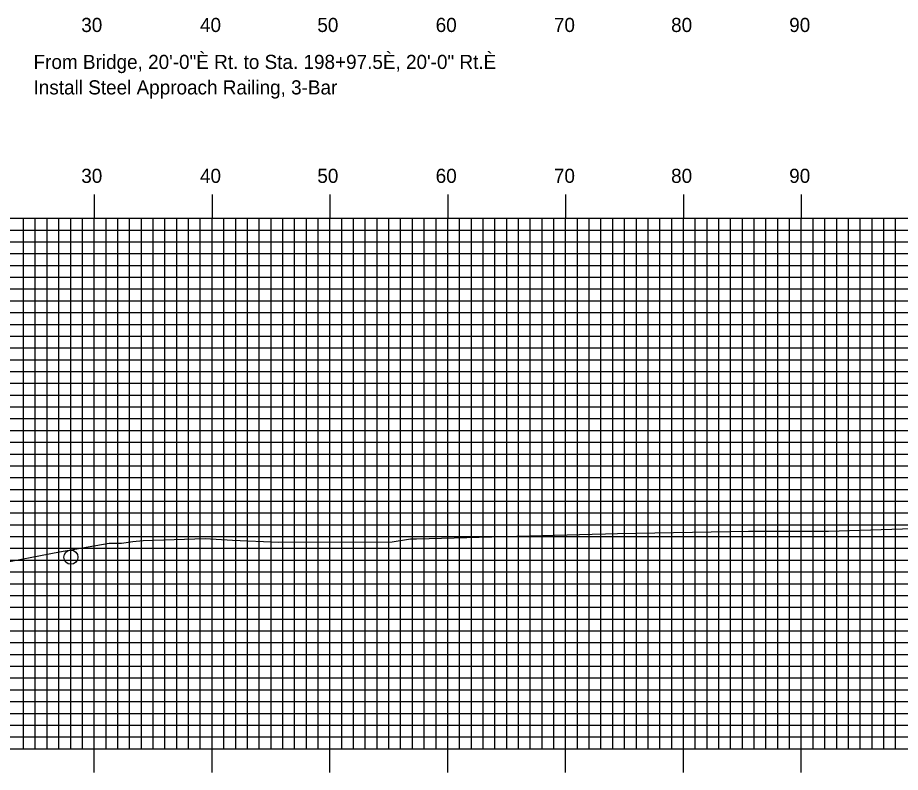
# Model space of a CAD drawing. Extents: x 1790124 to 1790467, y 442591 to 442811.
# Drawn here: x 1790313.2 to 1790388.1, y 442671.7 to 442735.7 of the extents above; entities that cross this region are included whole.
import ezdxf

# ---------------------------------------------------------------- set-up
doc = ezdxf.new("R2010")
doc.units = 0
for name, color, linetype in [('ANNOTATION', 7, 'Continuous'), ('H_V ANNOTATION', 7, 'Continuous'), ('MAJOR', 7, 'Continuous'), ('MINOR', 7, 'Continuous'), ('S_Drainage_Invert', 7, 'Continuous'), ('S_Roadway_Centerline', 7, 'Continuous')]:
    doc.layers.add(name, color=color, linetype=linetype)

msp = doc.modelspace()

# ---------------------------------------------------------------- linework, layer by layer
at = {"layer": 'MAJOR'}
for p, q in [((1790319.696, 442720.669), (1790319.696, 442718.665)), ((1790329.696, 442720.669), (1790329.696, 442718.665)), ((1790339.696, 442720.669), (1790339.696, 442718.665)), ((1790349.696, 442720.669), (1790349.696, 442718.665)), ((1790359.696, 442720.669), (1790359.696, 442718.665)), ((1790369.696, 442720.669), (1790369.696, 442718.665)), ((1790379.696, 442720.669), (1790379.696, 442718.665)), ((1790149.696, 442718.665), (1790429.696, 442718.665)), ((1790149.696, 442718.665), (1790429.696, 442718.665)), ((1790319.696, 442673.665), (1790319.696, 442718.665)), ((1790329.696, 442673.665), (1790329.696, 442718.665)), ((1790339.696, 442673.665), (1790339.696, 442718.665)), ((1790349.696, 442673.665), (1790349.696, 442718.665)), ((1790359.696, 442673.665), (1790359.696, 442718.665)), ((1790369.696, 442673.665), (1790369.696, 442718.665)), ((1790379.696, 442673.665), (1790379.696, 442718.665)), ((1790149.696, 442713.665), (1790429.696, 442713.665)), ((1790149.696, 442708.665), (1790429.696, 442708.665)), ((1790149.696, 442703.665), (1790429.696, 442703.665)), ((1790149.696, 442698.665), (1790429.696, 442698.665)), ((1790149.696, 442693.665), (1790429.696, 442693.665)), ((1790149.696, 442688.665), (1790429.696, 442688.665)), ((1790149.696, 442683.665), (1790429.696, 442683.665)), ((1790149.696, 442678.665), (1790429.696, 442678.665)), ((1790149.696, 442673.665), (1790429.696, 442673.665)), ((1790149.696, 442673.665), (1790429.696, 442673.665)), ((1790319.696, 442671.661), (1790319.696, 442673.665)), ((1790329.696, 442671.661), (1790329.696, 442673.665)), ((1790339.696, 442671.661), (1790339.696, 442673.665)), ((1790349.696, 442671.661), (1790349.696, 442673.665)), ((1790359.696, 442671.661), (1790359.696, 442673.665)), ((1790369.696, 442671.661), (1790369.696, 442673.665)), ((1790379.696, 442671.661), (1790379.696, 442673.665))]:
    msp.add_line(p, q, dxfattribs=at)
at = {"layer": 'MINOR'}
for p, q in [((1790313.696, 442673.665), (1790313.696, 442718.665)), ((1790314.696, 442673.665), (1790314.696, 442718.665)), ((1790315.696, 442673.665), (1790315.696, 442718.665)), ((1790316.696, 442673.665), (1790316.696, 442718.665)), ((1790317.696, 442673.665), (1790317.696, 442718.665)), ((1790318.696, 442673.665), (1790318.696, 442718.665)), ((1790320.696, 442673.665), (1790320.696, 442718.665)), ((1790321.696, 442673.665), (1790321.696, 442718.665)), ((1790322.696, 442673.665), (1790322.696, 442718.665)), ((1790323.696, 442673.665), (1790323.696, 442718.665)), ((1790324.696, 442673.665), (1790324.696, 442718.665)), ((1790325.696, 442673.665), (1790325.696, 442718.665)), ((1790326.696, 442673.665), (1790326.696, 442718.665)), ((1790327.696, 442673.665), (1790327.696, 442718.665)), ((1790328.696, 442673.665), (1790328.696, 442718.665)), ((1790330.696, 442673.665), (1790330.696, 442718.665)), ((1790331.696, 442673.665), (1790331.696, 442718.665)), ((1790332.696, 442673.665), (1790332.696, 442718.665)), ((1790333.696, 442673.665), (1790333.696, 442718.665)), ((1790334.696, 442673.665), (1790334.696, 442718.665)), ((1790335.696, 442673.665), (1790335.696, 442718.665)), ((1790336.696, 442673.665), (1790336.696, 442718.665)), ((1790337.696, 442673.665), (1790337.696, 442718.665)), ((1790338.696, 442673.665), (1790338.696, 442718.665)), ((1790340.696, 442673.665), (1790340.696, 442718.665)), ((1790341.696, 442673.665), (1790341.696, 442718.665)), ((1790342.696, 442673.665), (1790342.696, 442718.665)), ((1790343.696, 442673.665), (1790343.696, 442718.665)), ((1790344.696, 442673.665), (1790344.696, 442718.665)), ((1790345.696, 442673.665), (1790345.696, 442718.665)), ((1790346.696, 442673.665), (1790346.696, 442718.665)), ((1790347.696, 442673.665), (1790347.696, 442718.665)), ((1790348.696, 442673.665), (1790348.696, 442718.665)), ((1790350.696, 442673.665), (1790350.696, 442718.665)), ((1790351.696, 442673.665), (1790351.696, 442718.665)), ((1790352.696, 442673.665), (1790352.696, 442718.665)), ((1790353.696, 442673.665), (1790353.696, 442718.665)), ((1790354.696, 442673.665), (1790354.696, 442718.665)), ((1790355.696, 442673.665), (1790355.696, 442718.665)), ((1790356.696, 442673.665), (1790356.696, 442718.665)), ((1790357.696, 442673.665), (1790357.696, 442718.665)), ((1790358.696, 442673.665), (1790358.696, 442718.665)), ((1790360.696, 442673.665), (1790360.696, 442718.665)), ((1790361.696, 442673.665), (1790361.696, 442718.665)), ((1790362.696, 442673.665), (1790362.696, 442718.665)), ((1790363.696, 442673.665), (1790363.696, 442718.665)), ((1790364.696, 442673.665), (1790364.696, 442718.665)), ((1790365.696, 442673.665), (1790365.696, 442718.665)), ((1790366.696, 442673.665), (1790366.696, 442718.665)), ((1790367.696, 442673.665), (1790367.696, 442718.665)), ((1790368.696, 442673.665), (1790368.696, 442718.665)), ((1790370.696, 442673.665), (1790370.696, 442718.665)), ((1790371.696, 442673.665), (1790371.696, 442718.665)), ((1790372.696, 442673.665), (1790372.696, 442718.665)), ((1790373.696, 442673.665), (1790373.696, 442718.665)), ((1790374.696, 442673.665), (1790374.696, 442718.665)), ((1790375.696, 442673.665), (1790375.696, 442718.665)), ((1790376.696, 442673.665), (1790376.696, 442718.665)), ((1790377.696, 442673.665), (1790377.696, 442718.665)), ((1790378.696, 442673.665), (1790378.696, 442718.665)), ((1790380.696, 442673.665), (1790380.696, 442718.665)), ((1790381.696, 442673.665), (1790381.696, 442718.665)), ((1790382.696, 442673.665), (1790382.696, 442718.665)), ((1790383.696, 442673.665), (1790383.696, 442718.665)), ((1790384.696, 442673.665), (1790384.696, 442718.665)), ((1790385.696, 442673.665), (1790385.696, 442718.665)), ((1790386.696, 442673.665), (1790386.696, 442718.665)), ((1790387.696, 442673.665), (1790387.696, 442718.665)), ((1790149.696, 442717.665), (1790429.696, 442717.665)), ((1790149.696, 442716.665), (1790429.696, 442716.665)), ((1790149.696, 442715.665), (1790429.696, 442715.665)), ((1790149.696, 442714.665), (1790429.696, 442714.665)), ((1790149.696, 442712.665), (1790429.696, 442712.665)), ((1790149.696, 442711.665), (1790429.696, 442711.665)), ((1790149.696, 442710.665), (1790429.696, 442710.665)), ((1790149.696, 442709.665), (1790429.696, 442709.665)), ((1790149.696, 442707.665), (1790429.696, 442707.665)), ((1790149.696, 442706.665), (1790429.696, 442706.665)), ((1790149.696, 442705.665), (1790429.696, 442705.665)), ((1790149.696, 442704.665), (1790429.696, 442704.665)), ((1790149.696, 442702.665), (1790429.696, 442702.665)), ((1790149.696, 442701.665), (1790429.696, 442701.665)), ((1790149.696, 442700.665), (1790429.696, 442700.665)), ((1790149.696, 442699.665), (1790429.696, 442699.665)), ((1790149.696, 442697.665), (1790429.696, 442697.665)), ((1790149.696, 442696.665), (1790429.696, 442696.665)), ((1790149.696, 442695.665), (1790429.696, 442695.665)), ((1790149.696, 442694.665), (1790429.696, 442694.665)), ((1790149.696, 442692.665), (1790429.696, 442692.665)), ((1790149.696, 442691.665), (1790429.696, 442691.665)), ((1790149.696, 442690.665), (1790429.696, 442690.665)), ((1790149.696, 442689.665), (1790429.696, 442689.665)), ((1790149.696, 442687.665), (1790429.696, 442687.665)), ((1790149.696, 442686.665), (1790429.696, 442686.665)), ((1790149.696, 442685.665), (1790429.696, 442685.665)), ((1790149.696, 442684.665), (1790429.696, 442684.665)), ((1790149.696, 442682.665), (1790429.696, 442682.665)), ((1790149.696, 442681.665), (1790429.696, 442681.665)), ((1790149.696, 442680.665), (1790429.696, 442680.665)), ((1790149.696, 442679.665), (1790429.696, 442679.665)), ((1790149.696, 442677.665), (1790429.696, 442677.665)), ((1790149.696, 442676.665), (1790429.696, 442676.665)), ((1790149.696, 442675.665), (1790429.696, 442675.665)), ((1790149.696, 442674.665), (1790429.696, 442674.665))]:
    msp.add_line(p, q, dxfattribs=at)
at = {"layer": 'S_Drainage_Invert'}
msp.add_circle((1790317.714, 442689.914), 0.6, dxfattribs=at)
at = {"layer": 'S_Roadway_Centerline'}
msp.add_lwpolyline([(1790311.142, 442689.289), (1790316.737, 442690.355), (1790320.964, 442691.101), (1790322, 442691.101), (1790322.96, 442691.249), (1790323.848, 442691.321), (1790329.105, 442691.501), (1790331.435, 442691.364), (1790335.353, 442691.177), (1790344.975, 442691.215), (1790346.526, 442691.462), (1790347.027, 442691.471), (1790361.95, 442691.857), (1790363.08, 442691.884), (1790364.098, 442691.933), (1790375.216, 442692.109), (1790382.002, 442692.127), (1790398.113, 442692.634), (1790401.627, 442692.715), (1790404.68, 442692.904), (1790418.237, 442693.208), (1790429.696, 442694.282)], dxfattribs=at)

# ---------------------------------------------------------------- texts
at = {"layer": 'ANNOTATION'}
for s, p in [('From Bridge, 20\'-0"È Rt. to Sta. 198+97.5È, 20\'-0" Rt.È', (1790314.546, 442731.329)), ('Install Steel Approach Railing, 3-Bar', (1790314.546, 442729.169))]:
    msp.add_text(s, height=1.2, dxfattribs=at).set_placement(p)
at = {"layer": 'H_V ANNOTATION'}
for s, p in [('30', (1790318.593, 442734.465)), ('40', (1790328.668, 442734.465)), ('50', (1790338.625, 442734.465)), ('60', (1790348.668, 442734.465)), ('70', (1790358.7, 442734.465)), ('80', (1790368.647, 442734.465)), ('90', (1790378.668, 442734.465)), ('30', (1790318.593, 442721.665)), ('40', (1790328.668, 442721.665)), ('50', (1790338.625, 442721.665)), ('60', (1790348.668, 442721.665)), ('70', (1790358.7, 442721.665)), ('80', (1790368.647, 442721.665)), ('90', (1790378.668, 442721.665))]:
    msp.add_text(s, height=1.2, dxfattribs=at).set_placement(p)

doc.saveas('drawing.dxf')
